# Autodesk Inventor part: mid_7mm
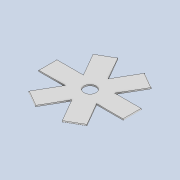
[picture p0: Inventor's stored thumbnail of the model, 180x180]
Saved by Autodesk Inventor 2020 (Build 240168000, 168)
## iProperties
Created: 2021-10
Part Number: mid_7mm
Material: Generic
Document SubType Name: Modeling
Designer: Shuang Peng
Density: 1 g/cm^3
Appearance: Default
Author: Shuang Peng
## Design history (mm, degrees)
sketch "Sketch1"
  geometry: C1 r 1.5 at (0, 0); 1 further point
  constraints: 1 centre point, 1 coincident
  dimensions: "d0" = 3 diameter of C1
extrude "Extrusion1" new body sketch "Sketch1" distance "d1" = 0.2; taper "d2" = 0 deg
sketch "Sketch2"
  geometry: L1 (0, 0)-(0, 0.1); L2 (0, 0.1)-(7, 0.1); L3 (0, 0)-(7, 0); L4 (7, 0.2)-(0, 0.2); L5 (1.5, 0.2)-(-1.5, 0.2) reference; A1 r 0.1 centre (0, 0.1) between (0, 0.2) and (0, 0); A2 r 0.1 centre (7, 0.1) between (7, 0) and (7, 0.2); 1 further point
  constraints: 10 end point, 4 point on circle, 4 tangent, 2 centre point, 1 collinear, 1 midpoint, 1 parallel, 1 vertical
  dimensions: "d3" = 0.1 distance of L1.start L1.end; "d4" = 7 distance of L1.end L2.end; "d5" = 0.2 diameter of A2
extrude "Extrusion2" join sketch "Sketch2" stored distance "d6" = 3; taper "d7" = 0 deg
pattern_circular "Circular Pattern1" dims angle "d9" = 360 deg
sketch "Sketch3"
  geometry: C1 r 1 at (0, 0); 1 further point
  constraints: 1 centre point, 1 coincident
  dimensions: "d11" = 2 diameter of C1
extrude "Extrusion3" cut sketch "Sketch3" distance "d12" = 3; taper "d13" = 0 deg
body "Solid1"
